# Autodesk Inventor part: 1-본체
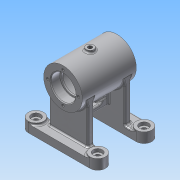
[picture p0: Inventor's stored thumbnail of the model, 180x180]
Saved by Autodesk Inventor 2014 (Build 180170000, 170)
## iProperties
Created: 2015-11
Part Number: 1-본체
Material: 알루미늄 6061
Document SubType Name: Modeling
Designer: 103-24
Mass: 358.167 g
Surface Area: 464.201 cm^2
Volume: 132.165 cm^3
Density: 2.71 g/cm^3
Appearance: 알루미늄 - 평지
Author: 103-24
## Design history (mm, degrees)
sketch "스케치1"
  geometry: L1 (50, -40)-(-50, -40); L2 (-50, -40)-(-50, 40); L3 (-50, 40)-(50, 40); L4 (50, 40)-(50, -40); L5 (50, -40)-(-50, 40); L6 (-50, -40)-(50, 40); 1 further point
  constraints: 12 end point, 2 midpoint, 2 parallel, 1 horizontal, 1 perpendicular
  dimensions: "d0" = 100 distance of L2.end L3.end; "d1" = 80 distance of L1.end L2.end
extrude "돌출1" new body sketch "스케치1" distance "d2" = 10; taper "d3" = 0 deg
node "작업 평면1"
sketch "스케치7"
  geometry: L1 (-50, -40)-(50, -40) reference; L2 (50, -40)-(50, 40) reference; L3 (50, 40)-(-50, 40) reference; L4 (-50, 40)-(-50, -40) reference; 1 further point
node "작업 평면8"
sketch "스케치13"
  geometry: 1 further point
node "작업 평면9"
sketch "스케치14"
  geometry: C1 r 25 at (0, 68); 1 further point
  constraints: 1 centre point, 1 vertical alignment
  dimensions: "d70" = 50 diameter of C1; "d71" = 68 distance of point (0, 0) C1.centre
extrude "돌출11" join sketch "스케치14" stored distance "d72" = 70; taper "d73" = 0 deg
sketch "스케치18"
  geometry: L1 (-50, -40)-(50, -40) reference; L2 (50, -40)-(50, 40) reference; L3 (50, 40)-(-50, 40) reference; L4 (-50, 40)-(-50, -40) reference; L5 (-40, 40)-(40, 40); L6 (-40, 40)-(-50, 40); L7 (-50, 40)-(-50, 30); L8 (-50, 30)-(-50, -30); L9 (-40, 20)-(40, 20); L10 (-50, -30)-(-50, -40); L11 (-50, -40)-(-40, -40); L12 (-40, -40)-(40, -40); L13 (-40, -20)-(40, -20); L14 (50, -40)-(50, -30); L15 (50, -40)-(40, -40); L16 (40, 40)-(50, 40); L17 (50, 40)-(50, 30); A1 r 10 centre (-40, 30) between (-40, 40) and (-50, 30); A2 r 10 centre (-40, -30) between (-50, -30) and (-40, -40); A3 r 10 centre (40, -30) between (40, -40) and (40, -20); A4 r 10 centre (40, 30) between (40, 40) and (40, 20); 1 further point
  constraints: 26 end point, 14 tangent, 12 point on circle, 8 point on line, 4 centre point, 2 collinear, 1 parallel, 1 perpendicular
  dimensions: "d98" = 20 diameter of A1; "d99" = 20 diameter of A2; "d100" = 20 diameter of A3; "d101" = 20 diameter of A4; "d102" = 80 distance of L9.start L9.end; "d103" = 80 distance of L13.start L13.end
extrude "돌출14" cut sketch "스케치18" distance "d104" = 50; taper "d105" = 0 deg
node "작업 평면12"
sketch "스케치19"
  geometry: L1 (35, 43)-(35, 93) reference; L2 (20, 10)-(20, 63.673); L3 (20, 63.673)-(28, 63.673); L4 (28, 63.673)-(28, 10); L5 (28, 10)-(20, 10); 1 further point
  constraints: 8 end point, 2 parallel, 2 perpendicular
  dimensions: "d107" = 8 distance of L2.end L3.end; "d167" = 53.67323 distance of L2.start L2.end
extrude "돌출15" join sketch "스케치19" stored distance "d108" = 50; taper "d109" = 0 deg
hole "구멍4" diameter "d76" = 28; stored, may be unused: countersink angle "d80" = 90 deg, drill point angle "d82" = 0 deg; dims "d74" = 10, "d75" = 10, "d77" = 8.608, "d78" = 32, "d79" = 12, "d81" = 14
sketch "스케치15"
  geometry: C1 r 14 at (0, 0) reference; C2 r 21 at (0, 0); 1 further point
  constraints: 1 centre point, 1 coincident
  dimensions: "d83" = 42 diameter of C2
extrude "돌출12" cut sketch "스케치15" distance "d84" = 42; taper "d85" = 0 deg
sketch "스케치16"
  geometry: C1 r 16 at (0, 0) reference; C2 r 25 at (0, 0) reference; A1 r 20 centre (0, 0) between (0, 20) and (0, -20); 3 further points
  constraints: 4 point on circle, 2 horizontal alignment, 2 vertical alignment, 1 centre point, 1 coincident
  dimensions: "d86" = 40 diameter of A1
hole "구멍5" sketch "스케치16" at (0, 20), (20, 0), (0, -20), (-20, 0) diameter "d87" = 3.242; stored, may be unused: countersink angle "d91" = 90 deg, drill point angle "d93" = 118 deg; dims "d88" = 8, "d89" = 32, "d90" = 12, "d92" = 10
sketch "스케치20"
  geometry: L1 (44, -43.322)-(44, -23); L2 (44, -23)-(36, -23); L3 (36, -23)-(36, -43.322); A1 r 25 centre (40, -68) between (64.623, -63.673) and (15.377, -63.673) reference; A2 r 25 centre (40, -68) between (64.623, -63.673) and (15.377, -63.673) reference; A3 r 25 centre (40, -68) between (44, -43.322) and (36, -43.322); 4 further points
  constraints: 6 end point, 4 point on circle, 2 perpendicular, 1 centre point, 1 coincident, 1 midpoint, 1 parallel, 1 vertical alignment
  dimensions: "d110" = 20 distance edge to line of A1 L2; "d111" = 8 distance of L1.end L2.end
extrude "돌출16" join sketch "스케치20" stored distance "d112" = 50; taper "d113" = 0 deg
sketch "스케치21"
  geometry: L1 (20.322, 0)-(20.322, 40) reference; L2 (6.822, 12)-(6.822, 28); L3 (13.822, 28)-(13.822, 12); L4 (43.322, -20)-(43.322, 0) reference; A1 r 3.5 centre (10.322, 28) between (13.822, 28) and (6.822, 28); A2 r 3.5 centre (10.322, 12) between (6.822, 12) and (13.822, 12); 2 further points
  constraints: 4 end point, 4 point on circle, 4 tangent, 2 centre point, 2 parallel, 1 horizontal alignment, 1 midpoint
  dimensions: "d114" = 23 dimension on A2 A1; "d115" = 33 distance from line of A2.centre L4; "d116" = 3.5 radius of A1
extrude "돌출17" cut sketch "스케치21" distance "d117" = 50; taper "d118" = 0 deg
sketch "스케치22"
  geometry: C1 r 10 at (-40, -30); C2 r 10 at (40, -30); A1 r 10 centre (-40, -30) between (-40, -20) and (-40, -40) reference; A2 r 10 centre (40, -30) between (40, -40) and (40, -20) reference; 1 further point
  constraints: 2 centre point, 2 coincident, 2 concentric
extrude "돌출18" join sketch "스케치22" distance "d119" = 3; taper "d120" = 0 deg
hole "구멍6" diameter "d123" = 6; stored, may be unused: countersink angle "d127" = 90 deg, drill point angle "d129" = 0 deg; dims "d121" = 10, "d122" = 10, "d124" = 8, "d125" = 12, "d126" = 4, "d128" = 10
node "작업 평면13"
sketch "스케치23"
  geometry: C1 r 5 at (0, 0); 1 further point
  constraints: 1 centre point, 1 coincident
  dimensions: "d131" = 10 diameter of C1
extrude "돌출19" join sketch "스케치23" stored distance "d132" = 3; taper "d133" = 0 deg
hole "구멍7" diameter "d136" = 5.188; stored, may be unused: countersink angle "d140" = 90 deg, drill point angle "d142" = 0 deg; dims "d137" = 8, "d138" = 2, "d139" = 4, "d141" = 10, "d149" = 10, "d150" = 10
node "작업 평면14"
sketch "스케치24"
  geometry: L1 (0, 68)-(-14, 43.751); L2 (0, 68)-(0, 0); C1 r 14 at (0, 68) reference
  constraints: 4 end point, 1 vertical
  dimensions: "d144" = 28 distance of L1.start L1.end; "d145" = 30 deg angle of L2 L1
node "작업 평면15"
sketch "스케치25"
  geometry: C1 r 6 at (0, 0); 2 further points
  constraints: 1 centre point, 1 coincident
  dimensions: "d146" = 12 diameter of C1
extrude "돌출20" join sketch "스케치25" stored distance "d147" = 3; taper "d148" = 0 deg
sketch "스케치26"
  geometry: C1 r 6 at (0, 0) reference; 2 further points
  constraints: 1 coincident
hole "구멍8" sketch "스케치26" at (0, 0) diameter "d151" = 5.188; stored, may be unused: countersink angle "d155" = 90 deg, drill point angle "d157" = 0 deg; dims "d152" = 8, "d153" = 2, "d154" = 4, "d156" = 10
fillet "모깎기3" dims "d160" = 2
fillet "모깎기4" dims "d161" = 0.3
fillet "모깎기5" dims "d162" = 2
fillet "모깎기6" dims "d163" = 0.3
chamfer "모따기1" distance "d164" = 1; stored, may be unused: second distance "d165" = 2, angle "d166" = 45 deg
fillet "모깎기7" dims "d168" = 2
fillet "모깎기8" dims "d169" = 2
fillet "모깎기9" dims "d170" = 2
fillet "모깎기10" dims "d171" = 2
node "작업 평면16"
node "작업 평면17"
sketch "스케치28"
  geometry: L1 (35, 93)-(-35, 93) reference; 2 further points
  constraints: 1 vertical alignment, 1 other
  dimensions: "d177" = 25 distance from line of L1 point (0, 68)
feature "엠보싱2" sketch "스케치28" dims "d73" = 0, "d178" = 0.5, "d179" = 0
node "솔리드1"
mirror "대칭7"
mirror "대칭5"
mirror "대칭6"
mirror "대칭8"
mirror "대칭9"
mirror "대칭10"
mirror "대칭11"
other parameters: "d4" = 0, "d68" = 0, "d69" = 0, "d106" = 0, "d130" = -96, "d143" = 0, "d172" = 53.5, "d176" = -80.5
